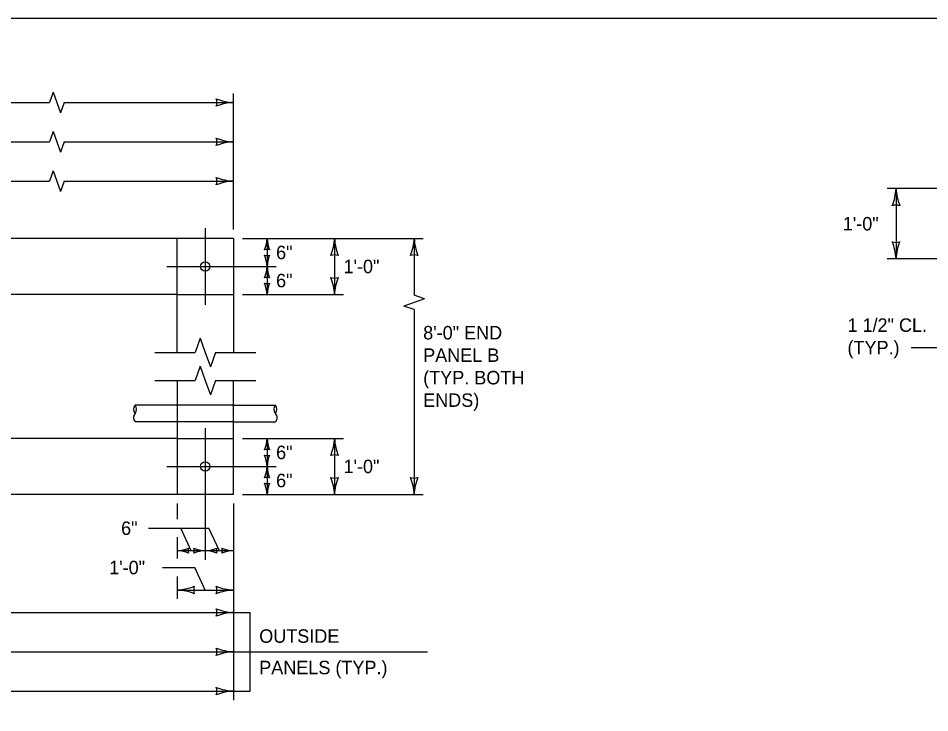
# Model space of a CAD drawing. Extents: x 49991.4 to 50021, y 49987.6 to 50011.4.
# Drawn here: x 50005.265 to 50009.32, y 49995.908 to 49998.999 of the extents above; entities that cross this region are included whole.
import ezdxf

# ---------------------------------------------------------------- set-up
doc = ezdxf.new("R2010")
doc.units = 0
for name, color, linetype in [('Level 1', 7, 'Continuous'), ('Level 2', 7, 'Continuous'), ('Level 3', 7, 'Continuous'), ('Level 4', 7, 'Continuous'), ('Level 5', 7, 'Continuous'), ('Level 6', 7, 'Continuous')]:
    doc.layers.add(name, color=color, linetype=linetype)

msp = doc.modelspace()

# ---------------------------------------------------------------- linework, layer by layer
at = {"layer": 'Level 1'}
for p, q in [((50006.2218, 49998.0191), (50005.1236, 49998.0191)), ((50005.9718, 49997.5116), (50005.9718, 49998.0191)), ((50006.2218, 49998.0191), (50006.2218, 49997.5116)), ((50005.9718, 49997.7691), (50005.1236, 49997.7691)), ((50005.9718, 49997.3866), (50005.9718, 49996.8791)), ((50006.2218, 49996.8791), (50006.2218, 49997.3866)), ((50005.9718, 49997.2773), (50005.7843, 49997.2773)), ((50006.2218, 49997.2773), (50006.4086, 49997.2773)), ((50005.9718, 49997.2023), (50005.7845, 49997.2023)), ((50006.2218, 49997.2023), (50006.4084, 49997.2023)), ((50005.9718, 49997.1291), (50005.1236, 49997.1291)), ((50006.2218, 49996.8791), (50005.1236, 49996.8791))]:
    msp.add_line(p, q, dxfattribs=at)
msp.add_lwpolyline([(49999.3835, 49998.9992), (50016.7501, 49998.9992), (50016.7501, 49987.7988), (49999.3835, 49987.7988)], close=True, dxfattribs=at)
for centre in [(50006.0967, 49997.8941), (50006.0967, 49997.0041)]:
    msp.add_circle(centre, 0.0208, dxfattribs=at)
for centre, radius, start, end in [((50005.8052, 49997.2585), 0.0281, 138.1897, 221.8103), ((50005.7633, 49997.2585), 0.0281, 318.1897, 41.8103), ((50006.4296, 49997.2585), 0.0281, 138.1897, 221.8103), ((50006.3877, 49997.2585), 0.0281, 318.1897, 41.8103), ((50005.8039, 49997.2212), 0.0271, 136.519, 224.2718), ((50006.3904, 49997.2211), 0.0261, 313.63, 45.5792)]:
    msp.add_arc(centre, radius, start, end, dxfattribs=at)
at = {"layer": 'Level 3'}
for p, q in [((50005.4204, 49998.6698), (50005.4042, 49998.6241)), ((50005.4204, 49998.6698), (50005.4366, 49998.6241)), ((50006.2218, 49998.0591), (50006.2218, 49998.6641)), ((50002.5536, 49998.6241), (50005.4042, 49998.6241)), ((50005.4366, 49998.6241), (50005.4528, 49998.5784)), ((50005.469, 49998.6241), (50005.4528, 49998.5784)), ((50005.469, 49998.6241), (50006.2218, 49998.6241)), ((50005.4204, 49998.4948), (50005.4042, 49998.4491)), ((50005.4204, 49998.4948), (50005.4366, 49998.4491)), ((50002.5534, 49998.4491), (50005.4042, 49998.4491)), ((50005.4366, 49998.4491), (50005.4528, 49998.4034)), ((50005.469, 49998.4491), (50005.4528, 49998.4034)), ((50005.469, 49998.4491), (50006.2218, 49998.4491)), ((50005.4203, 49998.3198), (50005.4041, 49998.2741)), ((50005.4203, 49998.3198), (50005.4365, 49998.2741)), ((50002.5539, 49998.2741), (50005.4041, 49998.2741)), ((50005.4365, 49998.2741), (50005.4527, 49998.2284)), ((50005.4689, 49998.2741), (50005.4527, 49998.2284)), ((50005.4689, 49998.2741), (50006.2218, 49998.2741)), ((50009.5801, 49998.2408), (50009.1301, 49998.2408)), ((50009.1701, 49998.2408), (50009.1701, 49997.9282)), ((50006.2618, 49998.0191), (50007.0663, 49998.0191)), ((50006.3718, 49998.0191), (50006.3718, 49997.8941)), ((50006.6718, 49998.0191), (50006.6718, 49997.7691)), ((50007.0263, 49998.0191), (50007.0263, 49997.7668)), ((50006.3718, 49997.8941), (50006.3718, 49997.7691)), ((50009.8825, 49997.9282), (50009.1301, 49997.9282)), ((50006.2618, 49997.7691), (50006.7118, 49997.7691)), ((50007.0263, 49997.7344), (50006.9806, 49997.7182)), ((50007.072, 49997.7506), (50007.0263, 49997.7668)), ((50007.072, 49997.7506), (50007.0263, 49997.7344)), ((50007.0263, 49997.702), (50006.9806, 49997.7182)), ((50007.0263, 49997.702), (50007.0263, 49996.8791)), ((50009.2378, 49997.5332), (50009.6201, 49997.5332)), ((50006.2618, 49997.1291), (50006.7118, 49997.1291)), ((50006.3718, 49997.1291), (50006.3718, 49997.0041)), ((50006.6718, 49997.1291), (50006.6718, 49996.8791)), ((50006.3718, 49997.0041), (50006.3718, 49996.8791)), ((50006.2618, 49996.8791), (50007.0663, 49996.8791)), ((50005.9718, 49996.8391), (50005.9718, 49996.7691)), ((50006.2218, 49996.8391), (50006.2218, 49995.9641)), ((50005.8435, 49996.7291), (50006.1125, 49996.7291)), ((50006.0343, 49996.6291), (50005.9875, 49996.7291)), ((50006.1593, 49996.6291), (50006.1125, 49996.7291)), ((50005.9718, 49996.6891), (50005.9718, 49996.5941)), ((50006.0968, 49996.6291), (50005.9718, 49996.6291)), ((50006.2218, 49996.6291), (50006.0968, 49996.6291)), ((50005.906, 49996.5541), (50006.05, 49996.5541)), ((50006.0968, 49996.4541), (50006.05, 49996.5541)), ((50005.9718, 49996.5141), (50005.9718, 49996.4141)), ((50005.9718, 49996.4541), (50006.2218, 49996.4541)), ((50003.8378, 49996.3541), (50006.2218, 49996.3541)), ((50006.2218, 49996.3541), (50006.2968, 49996.3541)), ((50006.2968, 49996.0041), (50006.2968, 49996.3541)), ((50003.8378, 49996.1791), (50006.2218, 49996.1791)), ((50006.2218, 49996.1791), (50007.0861, 49996.1791)), ((50003.8378, 49996.0041), (50006.2218, 49996.0041)), ((50006.2218, 49996.0041), (50006.2968, 49996.0041))]:
    msp.add_line(p, q, dxfattribs=at)
for centre, radius, start, end in [((50006.231, 49998.8462), 0.2223, 247.456, 267.6395), ((50006.0936, 49998.6241), 0.0548, 342.1388, 17.8612), ((50006.2333, 49998.3914), 0.233, 92.8273, 112.0772), ((50006.231, 49998.6712), 0.2223, 247.456, 267.6395), ((50006.0936, 49998.4491), 0.0548, 342.1388, 17.8612), ((50006.2333, 49998.2164), 0.233, 92.8273, 112.0772), ((50006.231, 49998.4962), 0.2223, 247.456, 267.6395), ((50006.0936, 49998.2741), 0.0548, 342.1388, 17.8612), ((50006.2333, 49998.0414), 0.233, 92.8273, 112.0772), ((50008.948, 49998.25), 0.2223, 337.456, 357.6395), ((50009.4028, 49998.2523), 0.233, 182.8273, 202.0772), ((50009.1701, 49998.1126), 0.0548, 72.1388, 107.8612), ((50006.2237, 49998.0252), 0.1482, 337.456, 357.6395), ((50006.5269, 49998.0268), 0.1553, 182.8273, 202.0772), ((50006.4497, 49998.0283), 0.2223, 337.456, 357.6395), ((50006.9045, 49998.0306), 0.233, 182.8273, 202.0772), ((50006.8042, 49998.0283), 0.2223, 337.456, 357.6395), ((50007.259, 49998.0306), 0.233, 182.8273, 202.0772), ((50009.1701, 49998.0564), 0.0548, 252.1388, 287.8612), ((50008.9374, 49997.9167), 0.233, 2.8273, 22.0772), ((50009.3922, 49997.919), 0.2223, 157.456, 177.6395), ((50006.3718, 49997.9336), 0.0365, 72.1388, 107.8612), ((50006.3718, 49997.9796), 0.0365, 252.1388, 287.8612), ((50006.2167, 49997.8864), 0.1553, 2.8273, 22.0772), ((50006.5199, 49997.888), 0.1482, 157.456, 177.6395), ((50006.6718, 49997.8909), 0.0548, 72.1388, 107.8612), ((50007.0263, 49997.8909), 0.0548, 72.1388, 107.8612), ((50006.2237, 49997.9002), 0.1482, 337.456, 357.6395), ((50006.5269, 49997.9018), 0.1553, 182.8273, 202.0772), ((50006.3718, 49997.8086), 0.0365, 72.1388, 107.8612), ((50006.3718, 49997.8546), 0.0365, 252.1388, 287.8612), ((50006.2167, 49997.7614), 0.1553, 2.8273, 22.0772), ((50006.5199, 49997.763), 0.1482, 157.456, 177.6395), ((50006.6718, 49997.8973), 0.0548, 252.1388, 287.8612), ((50006.4391, 49997.7576), 0.233, 2.8273, 22.0772), ((50006.8939, 49997.7599), 0.2223, 157.456, 177.6395), ((50006.2237, 49997.1352), 0.1482, 337.456, 357.6395), ((50006.5269, 49997.1368), 0.1553, 182.8273, 202.0772), ((50006.4497, 49997.1383), 0.2223, 337.456, 357.6395), ((50006.9045, 49997.1406), 0.233, 182.8273, 202.0772), ((50006.3718, 49997.0436), 0.0365, 72.1388, 107.8612), ((50006.3718, 49997.0896), 0.0365, 252.1388, 287.8612), ((50006.2167, 49996.9964), 0.1553, 2.8273, 22.0772), ((50006.5199, 49996.998), 0.1482, 157.456, 177.6395), ((50006.6718, 49997.0009), 0.0548, 72.1388, 107.8612), ((50006.2237, 49997.0102), 0.1482, 337.456, 357.6395), ((50006.5269, 49997.0118), 0.1553, 182.8273, 202.0772), ((50006.3718, 49996.9186), 0.0365, 72.1388, 107.8612), ((50006.3718, 49996.9646), 0.0365, 252.1388, 287.8612), ((50006.2167, 49996.8714), 0.1553, 2.8273, 22.0772), ((50006.5199, 49996.873), 0.1482, 157.456, 177.6395), ((50006.6718, 49997.0073), 0.0548, 252.1388, 287.8612), ((50006.4391, 49996.8676), 0.233, 2.8273, 22.0772), ((50006.8939, 49996.8699), 0.2223, 157.456, 177.6395), ((50007.0263, 49997.0073), 0.0548, 252.1388, 287.8612), ((50006.7936, 49996.8676), 0.233, 2.8273, 22.0772), ((50007.2484, 49996.8699), 0.2223, 157.456, 177.6395), ((50005.9641, 49996.7842), 0.1553, 272.8273, 292.0772), ((50006.0573, 49996.6291), 0.0365, 162.1388, 197.8612), ((50006.1029, 49996.7772), 0.1482, 247.456, 267.6395), ((50006.0113, 49996.6291), 0.0365, 342.1388, 17.8612), ((50006.0891, 49996.7842), 0.1553, 272.8273, 292.0772), ((50006.1823, 49996.6291), 0.0365, 162.1388, 197.8612), ((50006.2279, 49996.7772), 0.1482, 247.456, 267.6395), ((50006.1363, 49996.6291), 0.0365, 342.1388, 17.8612), ((50005.9657, 49996.481), 0.1482, 67.456, 87.6395), ((50006.1045, 49996.474), 0.1553, 92.8273, 112.0772), ((50006.0907, 49996.481), 0.1482, 67.456, 87.6395), ((50006.2295, 49996.474), 0.1553, 92.8273, 112.0772), ((50005.9603, 49996.6868), 0.233, 272.8273, 292.0772), ((50006.1, 49996.4541), 0.0548, 162.1388, 197.8612), ((50006.231, 49996.6762), 0.2223, 247.456, 267.6395), ((50006.0936, 49996.4541), 0.0548, 342.1388, 17.8612), ((50005.9626, 49996.232), 0.2223, 67.456, 87.6395), ((50006.2333, 49996.2214), 0.233, 92.8273, 112.0772), ((50006.231, 49996.5762), 0.2223, 247.456, 267.6395), ((50006.0936, 49996.3541), 0.0548, 342.1388, 17.8612), ((50006.2333, 49996.1214), 0.233, 92.8273, 112.0772), ((50006.231, 49996.4012), 0.2223, 247.456, 267.6395), ((50006.0936, 49996.1791), 0.0548, 342.1388, 17.8612), ((50006.2333, 49995.9464), 0.233, 92.8273, 112.0772), ((50006.231, 49996.2262), 0.2223, 247.456, 267.6395), ((50006.0936, 49996.0041), 0.0548, 342.1388, 17.8612), ((50006.2333, 49995.7714), 0.233, 92.8273, 112.0772)]:
    msp.add_arc(centre, radius, start, end, dxfattribs=at)
at = {"layer": 'Level 4'}
for p, q in [((50005.9718, 49997.7691), (50006.2218, 49997.7691)), ((50006.2218, 49997.2773), (50005.9718, 49997.2773)), ((50006.2218, 49997.2023), (50005.9718, 49997.2023)), ((50005.9718, 49997.1291), (50006.2218, 49997.1291))]:
    msp.add_line(p, q, dxfattribs=at)
at = {"layer": 'Level 5'}
for p, q in [((50006.0968, 49998.0649), (50006.0968, 49997.7232)), ((50005.9259, 49997.8941), (50006.4118, 49997.8941)), ((50006.0968, 49997.1749), (50006.0968, 49996.5891)), ((50005.9259, 49997.0041), (50006.4118, 49997.0041))]:
    msp.add_line(p, q, dxfattribs=at)
at = {"layer": 'Level 6'}
for p, q in [((50006.0741, 49997.5756), (50006.0514, 49997.5116)), ((50006.0741, 49997.5756), (50006.0968, 49997.5116)), ((50005.8718, 49997.5116), (50006.0514, 49997.5116)), ((50006.0968, 49997.5116), (50006.1195, 49997.4476)), ((50006.1422, 49997.5116), (50006.1195, 49997.4476)), ((50006.1422, 49997.5116), (50006.3218, 49997.5116)), ((50006.0741, 49997.4506), (50006.0514, 49997.3866)), ((50006.0741, 49997.4506), (50006.0968, 49997.3866)), ((50005.8718, 49997.3866), (50006.0514, 49997.3866)), ((50006.0968, 49997.3866), (50006.1195, 49997.3226)), ((50006.1422, 49997.3866), (50006.1195, 49997.3226)), ((50006.1422, 49997.3866), (50006.3218, 49997.3866))]:
    msp.add_line(p, q, dxfattribs=at)

# ---------------------------------------------------------------- texts
at = {"layer": 'Level 2'}
for s, p in [('1\'-0"', (50008.9332, 49998.0545)), ('6"', (50006.4118, 49997.9266)), ('1\'-0"', (50006.7118, 49997.8642)), ('6"', (50006.4118, 49997.8016)), ('1 1/2" CL.', (50008.9541, 49997.6032)), ('8\'-0" END', (50007.0663, 49997.5694)), ('(TYP.)', (50008.9541, 49997.5032)), ('PANEL B', (50007.0663, 49997.4694)), ('(TYP. BOTH', (50007.0663, 49997.3694)), ('ENDS)', (50007.0663, 49997.2694)), ('6"', (50006.4118, 49997.0366)), ('1\'-0"', (50006.7118, 49996.9742)), ('6"', (50006.4118, 49996.9116)), ('6"', (50005.7222, 49996.6991)), ('1\'-0"', (50005.6691, 49996.5241)), ('OUTSIDE', (50006.3368, 49996.2191)), ('PANELS (TYP.)', (50006.3368, 49996.0791))]:
    msp.add_text(s, height=0.06, dxfattribs=at).set_placement(p)

doc.saveas('drawing.dxf')
